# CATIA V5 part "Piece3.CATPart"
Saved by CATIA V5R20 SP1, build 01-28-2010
Part number: Piece3
Bounding box of the stored display mesh (mm): x -5 to 5, y 15.01 to 24.99, z 108.444 to 152.304
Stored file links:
  F:\TRAV\IAO\Exercice IAO\Catia\Piece3.CATPart
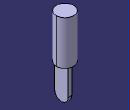
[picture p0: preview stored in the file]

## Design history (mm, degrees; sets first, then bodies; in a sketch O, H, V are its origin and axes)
Body1 (main body)
  Plane1: stored without definition
  Point1 "L": stored without definition
  Line1: stored without definition
  Line2: stored without definition
  Sketch1 on Plane1, origin (0, 0, 0), H (0, 1, 0), V (0, 0, 1)
    line L1 (16.1609, 127.3037) -> (16.1609, 112.2834)
    arc A1 centre (20, 112.2834) radius 3.8391 from (16.1609, 112.2834) to (23.8391, 112.2834) ccw
    point P3 (20, 112.2834)
    line L2 (23.8391, 112.2834) -> (23.8391, 127.3037)
    line L3 (23.8391, 127.3037) -> (16.1609, 127.3037)
    reference projected point E1 (20, 112.2834) from Point1
    reference projected line E3 (20, 112.2834) -> (20, 132.2834) from Line2
    reference projected line E4 (20, 112.2834) -> (20, 132.2834) from Line2
    tangency: A1 L1, L2 A1
    perpendicularity: L3 L1
    coincidence: P3 E1
    parallelism: L2 E3, E4 L1
  Pad1: profile Sketch1, direction (1, 0, 0), length 2
  Point2 "L": stored without definition
  DatumCurve1
  Sketch2 on start face of Pad1, origin (0, 0, 0), H (0, -1, 0), V (0, 0, 1)
    circle A1 centre (-20, 112.2834) radius 1.5
    point P1 (-20, 112.2834)
    reference projected point E1 (-20, 112.2834) from Point2
    reference projected circle E2 centre (-20, 112.2834) radius 1.5 from edge of DatumCurve1
    coincidence: E1 P1, A1 E2
  Pad2: profile Sketch2, direction (-1, 0, 0), length 2
  Point3 "L": stored without definition
  DatumCurve2
  Sketch3 on face of Pad1 from Sketch1.L3, origin (0, 0, 127.3037), H (1, 0, 0), V (0, 1, 0)
    circle A1 centre (0, 20) radius 5
    point P1 (0, 20)
    reference projected point E1 (0, 20) from Point3
    reference projected circle E2 centre (0, 20) radius 5 from edge of DatumCurve2
    coincidence: E1 P1, A1 E2
  Pad3: profile Sketch3, direction (0, 0, 1), length 25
